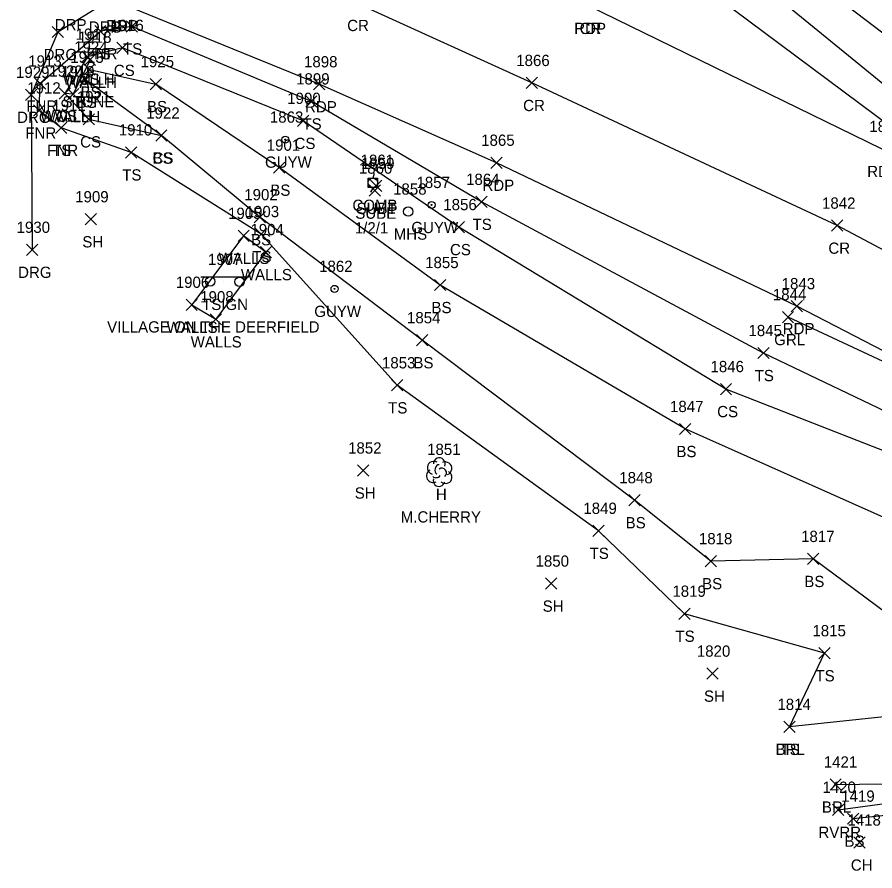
# Model space of a CAD drawing. Extents: x 1537342 to 1542195, y 163002 to 168596.
# Drawn here: x 1541531.9 to 1541684.3, y 163282.6 to 163434.2 of the extents above; entities that cross this region are included whole.
import ezdxf

# ---------------------------------------------------------------- set-up
doc = ezdxf.new("R2010")
doc.units = 0
for name, color, linetype in [('D_A', 7, 'Continuous'), ('D_C', 7, 'Continuous'), ('D_I', 7, 'Continuous'), ('D_TIC', 7, 'Continuous'), ('DHW', 7, 'Continuous'), ('L_A', 7, 'Continuous'), ('L_C', 7, 'Continuous'), ('L_I', 7, 'Continuous'), ('L_TIC', 7, 'Continuous'), ('LABL', 7, 'Continuous'), ('LAWE', 7, 'Continuous'), ('LELB', 7, 'Continuous'), ('LFNC', 7, 'Continuous'), ('LTD', 7, 'Continuous'), ('LWS', 7, 'Continuous'), ('P_A', 7, 'Continuous'), ('P_I', 7, 'Continuous'), ('P_TIC', 7, 'Continuous'), ('PET', 7, 'Continuous'), ('PRC', 7, 'Continuous'), ('R_A', 7, 'Continuous'), ('R_I', 7, 'Continuous'), ('R_TIC', 7, 'Continuous'), ('RDG', 7, 'Continuous'), ('RGR', 7, 'Continuous'), ('S_A', 7, 'Continuous'), ('S_C', 7, 'Continuous'), ('S_I', 7, 'Continuous'), ('SSGN', 7, 'Continuous'), ('U_A', 7, 'Continuous'), ('U_C', 7, 'Continuous'), ('U_I', 7, 'Continuous'), ('U_TIC', 7, 'Continuous'), ('UP', 7, 'Continuous'), ('UPGW', 7, 'Continuous'), ('USMH', 7, 'Continuous')]:
    doc.layers.add(name, color=color, linetype=linetype)

msp = doc.modelspace()

# ---------------------------------------------------------------- linework, layer by layer
at = {"layer": 'D_TIC'}
for points in [[(1541543.42, 163426.2), (1541545.42, 163428.2)], [(1541545.42, 163426.2), (1541543.42, 163428.2)], [(1541543.85, 163425.66), (1541545.85, 163427.66)], [(1541545.85, 163425.66), (1541543.85, 163427.66)], [(1541539.39, 163419.64), (1541541.39, 163421.64)], [(1541541.39, 163419.64), (1541539.39, 163421.64)], [(1541540.84, 163419.53), (1541542.84, 163421.53)], [(1541542.84, 163419.53), (1541540.84, 163421.53)]]:
    msp.add_lwpolyline(points, dxfattribs=at)
at = {"layer": 'DHW'}
msp.add_lwpolyline([(1541544.42, 163427.2), (1541544.85, 163426.66), (1541541.84, 163420.53), (1541540.39, 163420.64)], dxfattribs=at)
at = {"layer": 'L_TIC'}
for points in [[(1541551.3, 163431.58), (1541553.3, 163433.58)], [(1541553.3, 163431.58), (1541551.3, 163433.58)], [(1541545.69, 163430.72), (1541547.69, 163432.72)], [(1541547.69, 163430.72), (1541545.69, 163432.72)], [(1541545.69, 163430.72), (1541547.69, 163432.72)], [(1541547.69, 163430.72), (1541545.69, 163432.72)], [(1541549.64, 163427.77), (1541551.64, 163429.77)], [(1541551.64, 163427.77), (1541549.64, 163429.77)], [(1541543.42, 163426.2), (1541545.42, 163428.2)], [(1541545.42, 163426.2), (1541543.42, 163428.2)], [(1541543.73, 163423.91), (1541545.73, 163425.91)], [(1541545.73, 163423.91), (1541543.73, 163425.91)], [(1541535, 163421.43), (1541537, 163423.43)], [(1541537, 163421.43), (1541535, 163423.43)], [(1541543.03, 163422.1), (1541545.03, 163424.1)], [(1541545.03, 163422.1), (1541543.03, 163424.1)], [(1541555.53, 163421.33), (1541557.53, 163423.33)], [(1541557.53, 163421.33), (1541555.53, 163423.33)], [(1541555.53, 163421.33), (1541557.53, 163423.33)], [(1541557.53, 163421.33), (1541555.53, 163423.33)], [(1541539.39, 163419.64), (1541541.39, 163421.64)], [(1541541.39, 163419.64), (1541539.39, 163421.64)], [(1541583.18, 163418.26), (1541585.18, 163420.26)], [(1541585.18, 163418.26), (1541583.18, 163420.26)], [(1541534.82, 163416.65), (1541536.82, 163418.65)], [(1541536.82, 163416.65), (1541534.82, 163418.65)], [(1541543.66, 163415.07), (1541545.66, 163417.07)], [(1541545.66, 163415.07), (1541543.66, 163417.07)], [(1541581.75, 163414.8), (1541583.75, 163416.8)], [(1541583.75, 163414.8), (1541581.75, 163416.8)], [(1541538.71, 163413.57), (1541540.71, 163415.57)], [(1541540.71, 163413.57), (1541538.71, 163415.57)], [(1541538.71, 163413.57), (1541540.71, 163415.57)], [(1541540.71, 163413.57), (1541538.71, 163415.57)], [(1541556.53, 163412.19), (1541558.53, 163414.19)], [(1541558.53, 163412.19), (1541556.53, 163414.19)], [(1541556.53, 163412.19), (1541558.53, 163414.19)], [(1541558.53, 163412.19), (1541556.53, 163414.19)], [(1541551.17, 163409.2), (1541553.17, 163411.2)], [(1541553.17, 163409.2), (1541551.17, 163411.2)], [(1541577.45, 163406.49), (1541579.45, 163408.49)], [(1541579.45, 163406.49), (1541577.45, 163408.49)], [(1541613.42, 163400.42), (1541615.42, 163402.42)], [(1541615.42, 163400.42), (1541613.42, 163402.42)], [(1541543.99, 163397.32), (1541545.99, 163399.32)], [(1541545.99, 163397.32), (1541543.99, 163399.32)], [(1541574.03, 163397.69), (1541576.03, 163399.69)], [(1541576.03, 163397.69), (1541574.03, 163399.69)], [(1541609.38, 163395.93), (1541611.38, 163397.93)], [(1541611.38, 163395.93), (1541609.38, 163397.93)], [(1541571.15, 163394.38), (1541573.15, 163396.38)], [(1541573.15, 163394.38), (1541571.15, 163396.38)], [(1541574.28, 163394.69), (1541576.28, 163396.69)], [(1541576.28, 163394.69), (1541574.28, 163396.69)], [(1541575.12, 163391.49), (1541577.12, 163393.49)], [(1541577.12, 163391.49), (1541575.12, 163393.49)], [(1541575.12, 163391.49), (1541577.12, 163393.49)], [(1541577.12, 163391.49), (1541575.12, 163393.49)], [(1541606.09, 163385.64), (1541608.09, 163387.64)], [(1541608.09, 163385.64), (1541606.09, 163387.64)], [(1541561.92, 163382.13), (1541563.92, 163384.13)], [(1541563.92, 163382.13), (1541561.92, 163384.13)], [(1541566.2, 163379.55), (1541568.2, 163381.55)], [(1541568.2, 163379.55), (1541566.2, 163381.55)], [(1541566.2, 163379.55), (1541568.2, 163381.55)], [(1541568.2, 163379.55), (1541566.2, 163381.55)], [(1541602.88, 163375.84), (1541604.88, 163377.84)], [(1541604.88, 163375.84), (1541602.88, 163377.84)], [(1541663.55, 163373.56), (1541665.55, 163375.56)], [(1541665.55, 163373.56), (1541663.55, 163375.56)], [(1541598.42, 163367.83), (1541600.42, 163369.83)], [(1541600.42, 163367.83), (1541598.42, 163369.83)], [(1541656.86, 163367.16), (1541658.86, 163369.16)], [(1541658.86, 163367.16), (1541656.86, 163369.16)], [(1541649.61, 163360.07), (1541651.61, 163362.07)], [(1541651.61, 163360.07), (1541649.61, 163362.07)], [(1541592.41, 163352.7), (1541594.41, 163354.7)], [(1541594.41, 163352.7), (1541592.41, 163354.7)], [(1541640.59, 163347.42), (1541642.59, 163349.42)], [(1541642.59, 163347.42), (1541640.59, 163349.42)], [(1541634.22, 163341.99), (1541636.22, 163343.99)], [(1541636.22, 163341.99), (1541634.22, 163343.99)], [(1541672.34, 163336.99), (1541674.34, 163338.99)], [(1541674.34, 163336.99), (1541672.34, 163338.99)], [(1541654.18, 163336.59), (1541656.18, 163338.59)], [(1541656.18, 163336.59), (1541654.18, 163338.59)], [(1541625.8, 163332.61), (1541627.8, 163334.61)], [(1541627.8, 163332.61), (1541625.8, 163334.61)], [(1541649.47, 163327.26), (1541651.47, 163329.26)], [(1541651.47, 163327.26), (1541649.47, 163329.26)], [(1541674.35, 163320.24), (1541676.35, 163322.24)], [(1541676.35, 163320.24), (1541674.35, 163322.24)], [(1541654.46, 163316.62), (1541656.46, 163318.62)], [(1541656.46, 163316.62), (1541654.46, 163318.62)], [(1541668.13, 163307.16), (1541670.13, 163309.16)], [(1541670.13, 163307.16), (1541668.13, 163309.16)], [(1541668.13, 163307.16), (1541670.13, 163309.16)], [(1541670.13, 163307.16), (1541668.13, 163309.16)], [(1541676.36, 163296.92), (1541678.36, 163298.92)], [(1541678.36, 163296.92), (1541676.36, 163298.92)], [(1541676.78, 163292.44), (1541678.78, 163294.44)], [(1541678.78, 163292.44), (1541676.78, 163294.44)], [(1541679.48, 163290.86), (1541681.48, 163292.86)], [(1541681.48, 163290.86), (1541679.48, 163292.86)], [(1541680.57, 163286.62), (1541682.57, 163288.62)], [(1541682.57, 163286.62), (1541680.57, 163288.62)]]:
    msp.add_lwpolyline(points, dxfattribs=at)
at = {"layer": 'LABL'}
msp.add_lwpolyline([(1541677.36, 163297.92), (1541698.27, 163298.22), (1541716.95, 163301.17), (1541724.97, 163304.04), (1541725.24, 163309.57), (1541722.13, 163314.13), (1541698.82, 163311.33), (1541669.13, 163308.16)], dxfattribs=at)
at = {"layer": 'LAWE'}
msp.add_lwpolyline([(1541677.78, 163293.44), (1541698.28, 163296.18), (1541716.76, 163297.21), (1541728.01, 163299.94), (1541740.07, 163305.1), (1541745.43, 163310.81), (1541754.16, 163316.75), (1541763.56, 163326.93)], dxfattribs=at)
at = {"layer": 'LELB'}
for points in [[(1541813.12, 163355.49), (1541807.59, 163352.29), (1541792.75, 163363.67), (1541773.45, 163377.86), (1541766.85, 163384.06), (1541755.11, 163388.66), (1541717.31, 163411.39), (1541693.13, 163425.74), (1541646.55, 163461.21), (1541615.06, 163486.33), (1541589.07, 163507.09)], [(1541806.46, 163346.35), (1541770.85, 163375.53), (1541766.11, 163382.32), (1541753.11, 163384.46), (1541712.96, 163403.65), (1541689.28, 163419.49), (1541645.56, 163455.19), (1541611.14, 163481.6), (1541585.04, 163504.65)], [(1541762.76, 163328.26), (1541741.98, 163337.57), (1541701.3, 163356.94), (1541664.55, 163374.56), (1541614.42, 163401.42), (1541584.18, 163419.26), (1541552.3, 163432.58), (1541546.69, 163431.72)], [(1541753.68, 163328.14), (1541737.41, 163330.95), (1541699.36, 163351.91), (1541657.86, 163368.16), (1541610.38, 163396.93), (1541582.75, 163415.8), (1541550.64, 163428.77), (1541544.42, 163427.2), (1541540.39, 163420.64), (1541544.66, 163416.07), (1541557.53, 163413.19)], [(1541698.82, 163311.33), (1541690.14, 163325.55), (1541673.34, 163337.99), (1541655.18, 163337.59), (1541641.59, 163348.42), (1541603.88, 163376.84), (1541575.03, 163398.69), (1541557.53, 163413.19), (1541544.03, 163423.1), (1541544.73, 163424.91), (1541556.53, 163422.33)], [(1541743.53, 163322.21), (1541725.85, 163321.65), (1541695.19, 163341.2), (1541650.61, 163361.07), (1541607.09, 163386.64), (1541578.45, 163407.49), (1541556.53, 163422.33)], [(1541669.13, 163308.16), (1541675.35, 163321.24), (1541650.47, 163328.26), (1541635.22, 163342.99), (1541599.42, 163368.83), (1541575.28, 163395.69), (1541552.17, 163410.2), (1541539.71, 163414.57)], [(1541680.48, 163291.86), (1541699.97, 163293.9)]]:
    msp.add_lwpolyline(points, dxfattribs=at)
at = {"layer": 'LFNC'}
msp.add_lwpolyline([(1541539.71, 163414.57), (1541535.82, 163417.65), (1541536, 163422.43), (1541546.69, 163431.72)], dxfattribs=at)
at = {"layer": 'LTD'}
msp.add_line((1541606.88, 163353.45), (1541606.88, 163353.45), dxfattribs=at)
msp.add_line((1541606.88, 163353.45), (1541606.88, 163353.45), dxfattribs=at)
msp.add_arc((1541606.92, 163354.89), 1.05, 335.5272, 180.9563, dxfattribs=at)
for centre, major_axis, ratio, start_param, end_param in [((1541606.08, 163354.12), (1.21, -0.51), 0.895232, 1.570796, 4.712389), ((1541606.67, 163353.91), (-0.208, -0.792), 0.645439, 3.141593, 6.283185), ((1541607.38, 163353.29), (-0.5, 0.667), 0.989748, 3.141593, 6.283185), ((1541607.92, 163354.04), (-1.14, -0.48), 0.949671, 1.570796, 4.712389), ((1541605.79, 163352.74), (0.58, -1.04), 0.959034, 3.141593, 6.283185), ((1541606.42, 163352.7), (-0.625, -0.083), 0.423636, 0, 3.141593), ((1541607.88, 163352.62), (-1.09, 0.79), 0.841452, 1.570796, 4.712389), ((1541606.88, 163351.95), (0.26, 1.06), 0.942809, 1.570796, 4.712389)]:
    msp.add_ellipse(centre, major_axis=major_axis, ratio=ratio, start_param=start_param, end_param=end_param, dxfattribs=at)
at = {"layer": 'LWS'}
for points in [[(1541576.12, 163392.49), (1541572.15, 163395.38), (1541562.92, 163383.13), (1541567.2, 163380.55)], [(1541576.12, 163392.49), (1541567.2, 163380.55)]]:
    msp.add_lwpolyline(points, dxfattribs=at)
at = {"layer": 'P_TIC'}
for points in [[(1541584.57, 163421.3), (1541586.57, 163423.3)], [(1541586.57, 163421.3), (1541584.57, 163423.3)], [(1541622.38, 163421.53), (1541624.38, 163423.53)], [(1541624.38, 163421.53), (1541622.38, 163423.53)], [(1541616.1, 163407.36), (1541618.1, 163409.36)], [(1541618.1, 163407.36), (1541616.1, 163409.36)], [(1541676.63, 163396.19), (1541678.63, 163398.19)], [(1541678.63, 163396.19), (1541676.63, 163398.19)], [(1541669.45, 163381.89), (1541671.45, 163383.89)], [(1541671.45, 163381.89), (1541669.45, 163383.89)]]:
    msp.add_lwpolyline(points, dxfattribs=at)
at = {"layer": 'PET'}
for points in [[(1541702.01, 163402.19), (1541687.22, 163414.66), (1541642.2, 163448.26), (1541608.31, 163479.46), (1541580.56, 163501.03)], [(1541804.88, 163343.94), (1541781.94, 163357.9), (1541762.27, 163369.13), (1541719.07, 163393.38), (1541702.01, 163402.19), (1541685.47, 163410.81), (1541633.42, 163436.22), (1541598.66, 163451.94), (1541573.75, 163461.19), (1541557.97, 163467.97)], [(1541804.88, 163343.94), (1541786.3, 163336.28), (1541767.14, 163328.63), (1541744.37, 163342.88), (1541704.8, 163365.13), (1541670.45, 163382.89), (1541617.1, 163408.36), (1541585.57, 163422.3), (1541550.23, 163436.7), (1541542.2, 163439.81)]]:
    msp.add_lwpolyline(points, dxfattribs=at)
at = {"layer": 'PRC'}
msp.add_lwpolyline([(1541786.3, 163336.28), (1541753.03, 163356.38), (1541711.83, 163379.06), (1541677.63, 163397.19), (1541623.38, 163422.53), (1541592.11, 163436.74), (1541548.19, 163454.58)], dxfattribs=at)
at = {"layer": 'R_TIC'}
for points in [[(1541538.12, 163430.58), (1541540.12, 163432.58)], [(1541540.12, 163430.58), (1541538.12, 163432.58)], [(1541533.4, 163419.43), (1541535.4, 163421.43)], [(1541535.4, 163419.43), (1541533.4, 163421.43)], [(1541533.58, 163391.9), (1541535.58, 163393.9)], [(1541535.58, 163391.9), (1541533.58, 163393.9)], [(1541667.89, 163379.95), (1541669.89, 163381.95)], [(1541669.89, 163379.95), (1541667.89, 163381.95)]]:
    msp.add_lwpolyline(points, dxfattribs=at)
at = {"layer": 'RDG'}
msp.add_lwpolyline([(1541547.15, 163436.47), (1541539.12, 163431.58), (1541534.4, 163420.43), (1541534.58, 163392.9)], dxfattribs=at)
at = {"layer": 'RGR'}
msp.add_lwpolyline([(1541766.69, 163328.4), (1541744.13, 163342.08), (1541704.31, 163364.43), (1541668.89, 163380.95)], dxfattribs=at)
at = {"layer": 'SSGN'}
for p, q in [((1541564.56, 163388.12), (1541573.16, 163388.12)), ((1541568.58, 163387.22), (1541568.58, 163387.22))]:
    msp.add_line(p, q, dxfattribs=at)
for centre in [(1541566.22, 163387.29), (1541571.44, 163387.22)]:
    msp.add_circle(centre, 0.833, dxfattribs=at)
at = {"layer": 'U_TIC'}
for points in [[(1541594.46, 163402.41), (1541596.46, 163404.41)], [(1541596.46, 163402.41), (1541594.46, 163404.41)], [(1541594.72, 163403.25), (1541596.72, 163405.25)], [(1541596.72, 163403.25), (1541594.72, 163405.25)]]:
    msp.add_lwpolyline(points, dxfattribs=at)
at = {"layer": 'UP'}
for p, q in [((1541595.34, 163406.47), (1541595.09, 163405.64)), ((1541594.26, 163403.97), (1541594.26, 163405.64)), ((1541594.26, 163405.64), (1541595.93, 163405.64)), ((1541595.09, 163404.8), (1541595.09, 163404.8)), ((1541595.93, 163405.64), (1541595.93, 163403.97)), ((1541595.93, 163403.97), (1541594.26, 163403.97)), ((1541594.84, 163403.14), (1541595.09, 163403.97))]:
    msp.add_line(p, q, dxfattribs=at)
msp.add_circle((1541595.09, 163404.8), 0.833, dxfattribs=at)
at = {"layer": 'UPGW'}
for centre, radius in [((1541579.55, 163412.47), 0.625), ((1541579.55, 163412.47), 0.0833), ((1541605.55, 163400.86), 0.625), ((1541605.55, 163400.86), 0.0833), ((1541588.3, 163385.96), 0.625), ((1541588.3, 163385.96), 0.0833)]:
    msp.add_circle(centre, radius, dxfattribs=at)
at = {"layer": 'USMH'}
for p, q in [((1541601.4, 163399.69), (1541601.4, 163399.69)), ((1541602.23, 163399.69), (1541602.23, 163399.69))]:
    msp.add_line(p, q, dxfattribs=at)
msp.add_circle((1541601.4, 163399.69), 0.833, dxfattribs=at)

# ---------------------------------------------------------------- texts
at = {"layer": 'D_A'}
for p in [(1541540.01, 163422.2), (1541540.44, 163421.66), (1541535.98, 163415.64), (1541537.44, 163415.53)]:
    msp.add_text('WALLH', height=2, dxfattribs=at).set_placement(p)
at = {"layer": 'D_C'}
msp.add_text('STONE', height=2, dxfattribs=at).set_placement((1541539.97, 163418.2))
at = {"layer": 'D_I'}
for s, p in [('1917', (1541542.3, 163430.2)), ('1918', (1541542.73, 163429.66)), ('1920', (1541537.61, 163423.64)), ('1919', (1541539.71, 163423.53))]:
    msp.add_text(s, height=2, dxfattribs=at).set_placement(p)
at = {"layer": 'L_A'}
for s, p in [('TS', (1541545.1, 163426.72)), ('TS', (1541550.71, 163427.58)), ('FNR', (1541544.23, 163426.72)), ('CS', (1541549.08, 163423.77)), ('CS', (1541542.86, 163422.2)), ('BS', (1541543.17, 163419.91)), ('BS', (1541542.47, 163418.1)), ('FNR', (1541533.53, 163417.43)), ('BS', (1541554.97, 163417.33)), ('BS', (1541554.97, 163417.33)), ('CS', (1541538.83, 163415.64)), ('TS', (1541582.59, 163414.26)), ('FNR', (1541533.35, 163412.65)), ('CS', (1541543.1, 163411.07)), ('CS', (1541581.19, 163410.8)), ('FNR', (1541537.24, 163409.57)), ('TS', (1541538.11, 163409.57)), ('CS', (1541555.97, 163408.19)), ('BS', (1541555.97, 163408.19)), ('TS', (1541550.58, 163405.2)), ('BS', (1541576.89, 163402.49)), ('TS', (1541612.83, 163396.42)), ('SH', (1541543.48, 163393.32)), ('BS', (1541573.47, 163393.69)), ('CS', (1541608.82, 163391.93)), ('WALLS', (1541567.69, 163390.38)), ('TS', (1541573.69, 163390.69)), ('WALLS', (1541571.66, 163387.49)), ('WALLS', (1541571.66, 163387.49)), ('BS', (1541605.53, 163381.64)), ('WALLS', (1541558.46, 163378.13)), ('WALLS', (1541562.74, 163375.55)), ('WALLS', (1541562.74, 163375.55)), ('BS', (1541602.32, 163371.84)), ('TS', (1541662.96, 163369.56)), ('TS', (1541597.83, 163363.83)), ('CS', (1541656.3, 163363.16)), ('BS', (1541649.05, 163356.07)), ('SH', (1541591.89, 163348.7)), ('H', (1541606.31, 163348.45)), ('BS', (1541640.03, 163343.42)), ('TS', (1541633.63, 163337.99)), ('BS', (1541653.62, 163332.59)), ('BS', (1541671.78, 163332.99)), ('SH', (1541625.29, 163328.61)), ('TS', (1541648.88, 163323.26)), ('TS', (1541673.76, 163316.24)), ('SH', (1541653.95, 163312.62)), ('BRL', (1541666.67, 163303.16)), ('TS', (1541667.54, 163303.16)), ('BRL', (1541674.91, 163292.92)), ('RVRR', (1541674.29, 163288.44)), ('BS', (1541678.92, 163286.86)), ('CH', (1541680.05, 163282.62))]:
    msp.add_text(s, height=2, dxfattribs=at).set_placement(p)
at = {"layer": 'L_C'}
msp.add_text('M.CHERRY', height=2, dxfattribs=at).set_placement((1541600.06, 163344.45))
at = {"layer": 'L_I'}
for s, p in [('1916', (1541548.46, 163431.77)), ('1917', (1541542.3, 163430.2)), ('1924', (1541542.03, 163427.91)), ('1913', (1541533.87, 163425.43)), ('1923', (1541541.34, 163426.1)), ('1925', (1541553.84, 163425.33)), ('1925', (1541553.84, 163425.33)), ('1920', (1541537.61, 163423.64)), ('1899', (1541581.48, 163422.26)), ('1912', (1541533.69, 163420.65)), ('1911', (1541538.15, 163417.57)), ('1911', (1541538.15, 163417.57)), ('1921', (1541542.53, 163419.07)), ('1900', (1541579.89, 163418.8)), ('1922', (1541554.84, 163416.19)), ('1922', (1541554.84, 163416.19)), ('1910', (1541549.96, 163413.2)), ('1901', (1541576.25, 163410.49)), ('1864', (1541611.68, 163404.42)), ('1909', (1541542.21, 163401.32)), ('1902', (1541572.26, 163401.69)), ('1856', (1541607.63, 163399.93)), ('1905', (1541569.38, 163398.38)), ('1903', (1541572.51, 163398.69)), ('1904', (1541573.35, 163395.49)), ('1904', (1541573.35, 163395.49)), ('1855', (1541604.4, 163389.64)), ('1906', (1541560.09, 163386.13)), ('1908', (1541564.43, 163383.55)), ('1908', (1541564.43, 163383.55)), ('1854', (1541601.18, 163379.84)), ('1845', (1541661.86, 163377.56)), ('1853', (1541596.73, 163371.83)), ('1846', (1541655.11, 163371.16)), ('1847', (1541647.92, 163364.07)), ('1852', (1541590.71, 163356.7)), ('1851', (1541604.75, 163356.45)), ('1848', (1541638.9, 163351.42)), ('1849', (1541632.52, 163345.99)), ('1818', (1541653.05, 163340.59)), ('1817', (1541671.21, 163340.99)), ('1850', (1541624.02, 163336.61)), ('1819', (1541648.34, 163331.26)), ('1815', (1541673.22, 163324.24)), ('1820', (1541652.68, 163320.62)), ('1814', (1541667, 163311.16)), ('1814', (1541667, 163311.16)), ('1421', (1541675.24, 163300.92)), ('1420', (1541675, 163296.44)), ('1419', (1541678.34, 163294.86)), ('1418', (1541679.44, 163290.62))]:
    msp.add_text(s, height=2, dxfattribs=at).set_placement(p)
at = {"layer": 'P_A'}
for s, p in [('RDP', (1541547.72, 163431.7)), ('CR', (1541590.55, 163431.74)), ('RDP', (1541630.9, 163431.22)), ('CR', (1541631.85, 163431.22)), ('RDP', (1541583.06, 163417.3)), ('CR', (1541621.82, 163417.53)), ('RDP', (1541682.96, 163405.81)), ('RDP', (1541614.59, 163403.36)), ('CR', (1541676.06, 163392.19)), ('RDP', (1541667.94, 163377.89))]:
    msp.add_text(s, height=2, dxfattribs=at).set_placement(p)
at = {"layer": 'P_I'}
for s, p in [('1898', (1541582.88, 163425.3)), ('1866', (1541620.59, 163425.53)), ('1841', (1541683.34, 163413.81)), ('1865', (1541614.36, 163411.36)), ('1842', (1541674.93, 163400.19)), ('1843', (1541667.76, 163385.89))]:
    msp.add_text(s, height=2, dxfattribs=at).set_placement(p)
at = {"layer": 'R_A'}
for s, p in [('DRP', (1541538.59, 163431.88)), ('DRG', (1541544.63, 163431.47)), ('DRP', (1541544.63, 163431.47)), ('DRP', (1541547.72, 163431.7)), ('DRG', (1541536.61, 163426.58)), ('DRG', (1541531.89, 163415.43)), ('DRG', (1541532.07, 163387.9)), ('GRL', (1541666.43, 163375.95))]:
    msp.add_text(s, height=2, dxfattribs=at).set_placement(p)
at = {"layer": 'R_I'}
for s, p in [('1929', (1541531.7, 163423.43)), ('1930', (1541531.8, 163395.9)), ('1844', (1541666.19, 163383.95))]:
    msp.add_text(s, height=2, dxfattribs=at).set_placement(p)
at = {"layer": 'S_A'}
msp.add_text('TSIGN', height=2, dxfattribs=at).set_placement((1541564.76, 163382.2))
at = {"layer": 'S_C'}
msp.add_text('VILLAGE ON THE DEERFIELD', height=2, dxfattribs=at).set_placement((1541547.89, 163378.2))
at = {"layer": 'S_I'}
msp.add_text('1907', height=2, dxfattribs=at).set_placement((1541565.81, 163390.2))
at = {"layer": 'U_A'}
for s, p in [('GUYW', (1541575.95, 163407.47)), ('COMB', (1541591.48, 163399.8)), ('SUBE', (1541591.99, 163398.41)), ('SUBT', (1541592.22, 163399.25)), ('GUYW', (1541601.95, 163395.86)), ('MHS', (1541598.82, 163394.69)), ('GUYW', (1541584.7, 163380.96))]:
    msp.add_text(s, height=2, dxfattribs=at).set_placement(p)
at = {"layer": 'U_C'}
msp.add_text('1/2/1', height=2, dxfattribs=at).set_placement((1541591.91, 163395.8))
at = {"layer": 'U_I'}
for s, p in [('1863', (1541576.81, 163415.47)), ('1861', (1541592.92, 163407.8)), ('1859', (1541593.02, 163407.25)), ('1860', (1541592.63, 163406.41)), ('1857', (1541602.86, 163403.86)), ('1858', (1541598.71, 163402.69)), ('1862', (1541585.56, 163388.96))]:
    msp.add_text(s, height=2, dxfattribs=at).set_placement(p)

doc.saveas('drawing.dxf')
